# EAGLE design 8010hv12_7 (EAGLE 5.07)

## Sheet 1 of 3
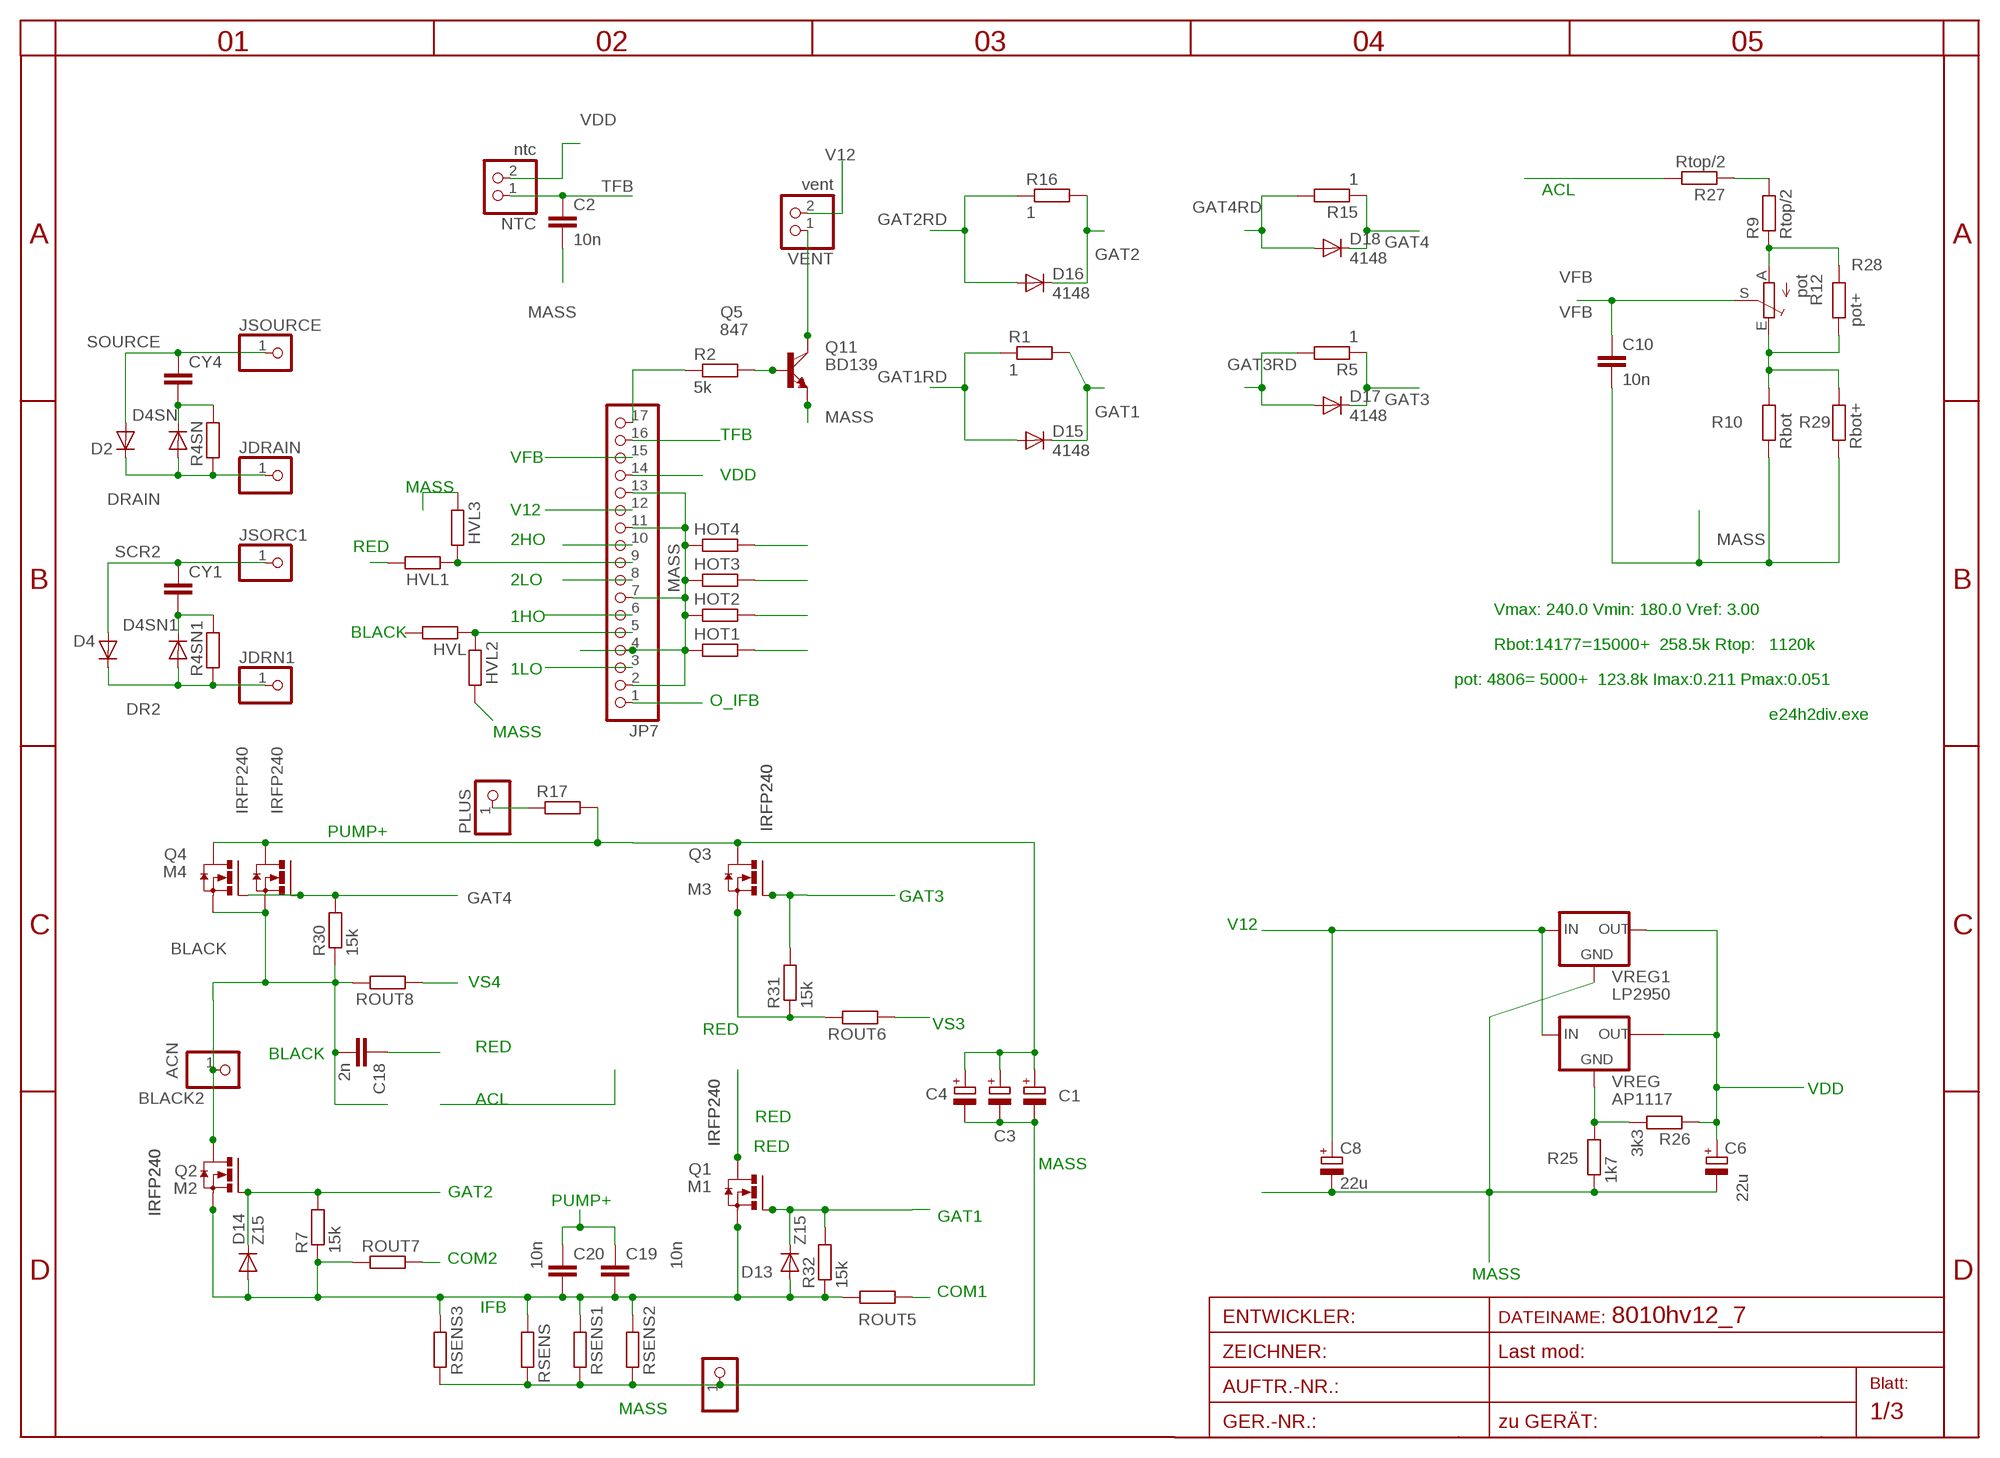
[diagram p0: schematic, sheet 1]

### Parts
BLACK2  ACN  PINHD-1X12MM2  [1X2MM2]
C1  CPOL-EUE5-13  [E5-13]
C2  10n  C-EUC0805  [C0805]
C3  CPOL-EUE5-13  [E5-13]
C4  CPOL-EUE5-13  [E5-13]
C6  22u  CPOL-EUSMCA  [SMC_A]
C8  22u  CPOL-EUSMCA  [SMC_A]
C10  10n  C-EUC0805  [C0805]
C18  2n  C-EU050-024X044  [C050-024X044]
C19  10n  C-EU050-024X044  [C050-024X044]
C20  10n  C-EU050-024X044  [C050-024X044]
CY1  CXXC10B5  [XC10B5]
CY4  CXXC10B5  [XC10B5]
D2  DIODE-TO220V  [TO220ACS]
D4  DIODE-TO220V  [TO220ACS]
D4SN  DIODE-P1-10  [P1-10]
D4SN1  DIODE-P1-10  [P1-10]
D13  Z15  DIODE-MINIMELF  [MINIMELF]
D14  Z15  DIODE-MINIMELF  [MINIMELF]
D15  4148  DIODE-MINIMELF  [MINIMELF]
D16  4148  DIODE-MINIMELF  [MINIMELF]
D17  4148  DIODE-MINIMELF  [MINIMELF]
D18  4148  DIODE-MINIMELF  [MINIMELF]
HOT1  R-EU_R0805  [R0805]
HOT2  R-EU_R0805  [R0805]
HOT3  R-EU_R0805  [R0805]
HOT4  R-EU_R0805  [R0805]
HVL  R-EU_R1005  [R1005]
HVL1  R-EU_R1005  [R1005]
HVL2  R-EU_R0805  [R0805]
HVL3  R-EU_R0805  [R0805]
JDRAIN  PINHD-1X11MM0  [1X1MM0]
JDRN1  PINHD-1X11MM0  [1X1MM0]
JP7  PINHD-1X17  [1X17]
JSORC1  PINHD-1X11MM0  [1X1MM0]
JSOURCE  PINHD-1X11MM0  [1X1MM0]
M1  IRFP240  [TO247BV]
M2  IRFP240  [TO247BV]
M3  IRFP240  [TO247BV]
M4  IRFP240  [TO247BV]
MINUS  PINHD-1X12MM3  [1X2MM3]
NTC  ntc  PINHD-1X2STR  [1X02]
PLUS  PINHD-1X12MM3  [1X2MM3]
Q1  IRFP240  [TO247BV]
Q2  IRFP240  [TO247BV]
Q3  IRFP240  [TO247BV]
Q4  IRFP240  [TO247BV]
Q5  847  BC847SMD  [SOT23]
Q11  BD139  [TO126AV]
R1  1  R-EU_R2512  [R2512]
R2  5k  R-EU_R0805  [R0805]
R4SN  R-EU_0207/10  [0207/10]
R4SN1  R-EU_0207/10  [0207/10]
R5  1  R-EU_R2512  [R2512]
R7  15k  R-EU_R1206  [R1206]
R9  Rtop/2  R-EU_R1206  [R1206]
R10  Rbot  R-EU_R0805  [R0805]
R12  pot  TRIM_EU-B64Y  [B64Y]
R15  1  R-EU_R2512  [R2512]
R16  1  R-EU_R2512  [R2512]
R17  R-EU_0309/10  [0309/10]
R25  1k7  R-EU_R0805  [R0805]
R26  3k3  R-EU_R0805  [R0805]
R27  Rtop/2  R-EU_R1206  [R1206]
R28  pot+  R-EU_R0805  [R0805]
R29  Rbot+  R-EU_R0805  [R0805]
R30  15k  R-EU_R1206  [R1206]
R31  15k  R-EU_R1206  [R1206]
R32  15k  R-EU_R1206  [R1206]
ROUT5  R-EU_R2512  [R2512]
ROUT6  R-EU_R2512  [R2512]
ROUT7  R-EU_R2512  [R2512]
ROUT8  R-EU_R2512  [R2512]
RSENS  R-EU_WIRE  [WIRE]
RSENS1  R-EU_0309/10  [0309/10]
RSENS2  R-EU_0309/12  [0309/12]
RSENS3  R-EU_R2512  [R2512]
VENT  vent  PINHD-1X2STR  [1X02]
VREG  AP1117  [SOT223]
VREG1  LP2950  LP2950TO92-2MIL  [TO92-2MIL]

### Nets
1HO: HOT2.2 JP7.6 ; also sheet 3
1LO: HOT1.2 JP7.3 ; also sheet 3
2HO: HOT4.2 JP7.10 ; also sheet 3
2LO: HOT3.2 JP7.8 ; also sheet 3
ACL: R27.2
BLACK: BLACK2.1 C18.2 HVL.2 M2.D M4.S Q2.D Q4.S R30.1 ROUT8.2
COM1: ROUT5.1 ; also sheet 3
COM2: ROUT7.2 ; also sheet 3
DFG: HVL1.1 HVL3.2 JP7.9
DR2: D4.C D4SN1.A JDRN1.1 R4SN1.1
DRAIN: D2.C D4SN.A JDRAIN.1 R4SN.1
GAT1: D13.C D15.C M1.G Q1.G R1.2 R32.2
GAT1RD: D15.A R1.1 ; also sheet 3
GAT2: D14.C D16.C M2.G Q2.G R7.2 R16.2
GAT2RD: D16.A R16.1 ; also sheet 3
GAT3: D17.C M3.G Q3.G R5.1 R31.2
GAT3RD: D17.A R5.2 ; also sheet 3
GAT4: D18.C M4.G Q4.G R15.1 R30.2
GAT4RD: D18.A R15.2 ; also sheet 3
IFB: C19.2 C20.2 D13.A D14.A M1.S M2.S Q1.S Q2.S R7.1 R32.1 ROUT5.2 ROUT7.1 RSENS1.1 RSENS2.1 RSENS3.1 RSENS.1 ; also sheet 3
JDH: HVL2.1 HVL.1 JP7.5
MASS: C1.- C2.2 C3.- C4.- C6.- C8.- C10.2 HOT1.1 HOT2.1 HOT3.1 HOT4.1 HVL2.2 HVL3.1 JP7.2 JP7.4 JP7.7 JP7.11 JP7.13 MINUS.1 Q5.2(E) Q11.E R10.1 R25.1 R29.1 RSENS1.2 RSENS2.2 RSENS3.2 RSENS.2 VREG1.2(GND) ; also sheet 2,3
N$1: Q5.3(C) Q11.C VENT.1
N$2: Q5.1(B) Q11.B R2.2
N$3: JP7.17 R2.1
N$5: PLUS.1 R17.1
N$17: R25.2 R26.2 VREG.1(GND)
N$23: R9.2 R27.1
N$29: R10.2 R12.E R28.1 R29.2
N$30: R9.1 R12.A R28.2
O_IFB: JP7.1 ; also sheet 3
PUMP+: C1.+ C3.+ C4.+ C19.1 C20.1 M3.D M4.D Q3.D Q4.D R17.2 ; also sheet 2
RED: C18.1 HVL1.2 M1.D M3.S Q1.D Q3.S R31.1 ROUT6.2
SCR2: CY1.1 D4.A JSORC1.1
SNUB1: CY1.2 D4SN1.C R4SN1.2
SNUB2: CY4.2 D4SN.C R4SN.2
SOURCE: CY4.1 D2.A JSOURCE.1
TFB: C2.1 JP7.16 NTC.1
V12: C8.+ JP7.12 VENT.2 VREG1.3(IN) VREG.3(IN) ; also sheet 2,3
VDD: C6.+ JP7.14 NTC.2 R26.1 VREG1.1(OUT) VREG.4(TAB) ; also sheet 3
VFB: C10.1 JP7.15 R12.S
VS3: ROUT6.1 ; also sheet 3
VS4: ROUT8.1 ; also sheet 3
Unconnected: VREG.2(OUT)

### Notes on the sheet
- Vmax: 240.0 Vmin: 180.0 Vref: 3.00
- Rbot:14177=15000+  258.5k Rtop:   1120k
- pot: 4806= 5000+  123.8k Imax:0.211 Pmax:0.051
- e24h2div.exe

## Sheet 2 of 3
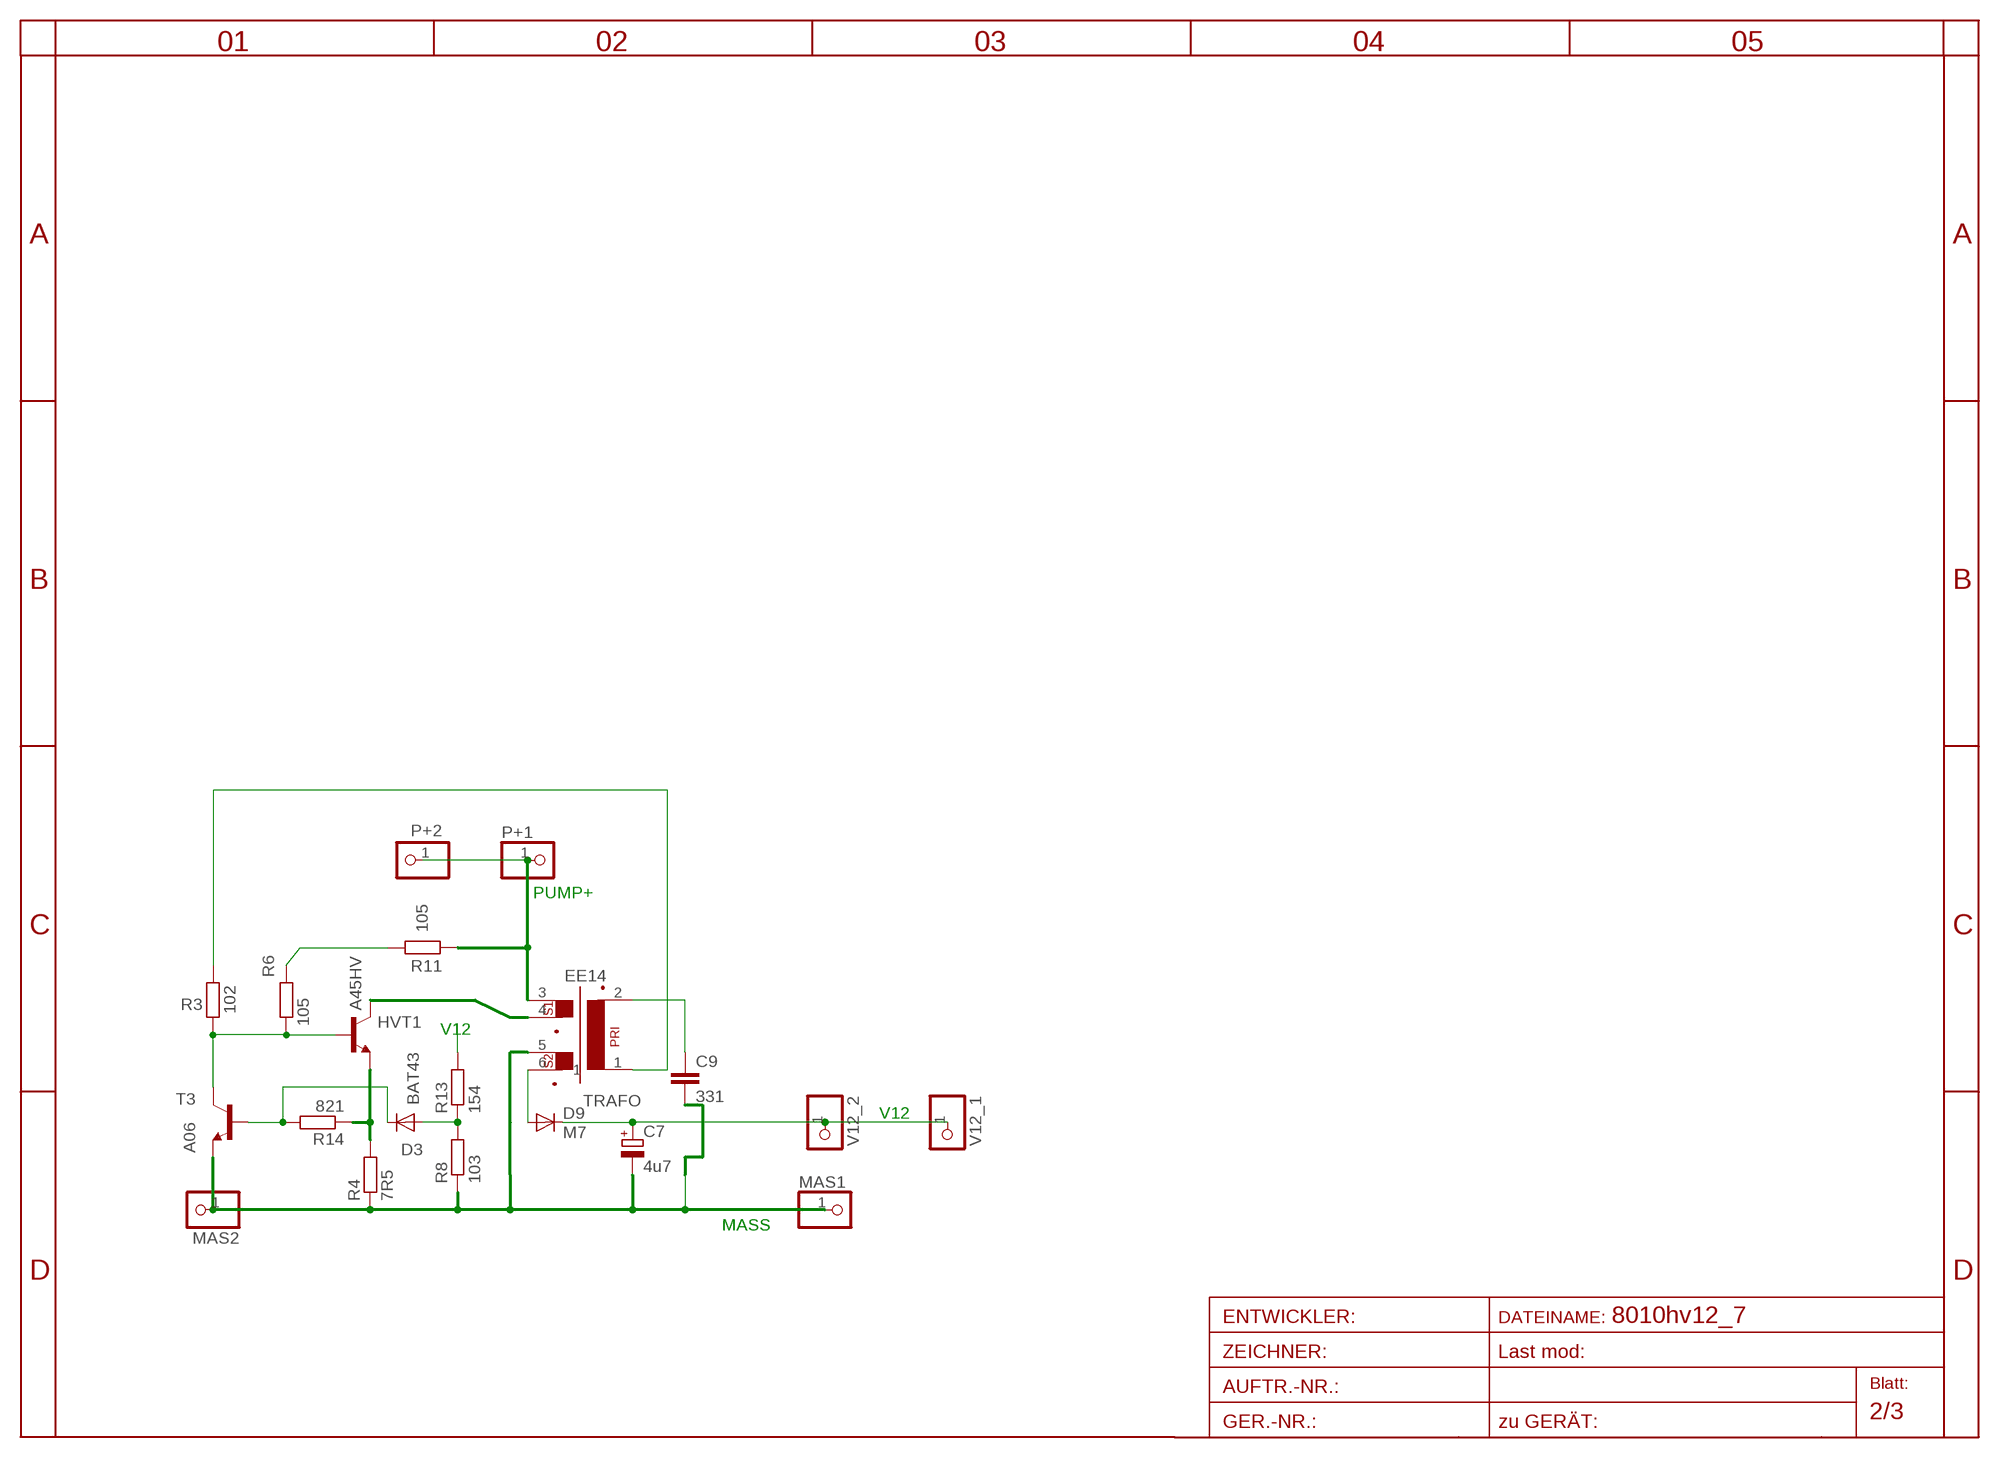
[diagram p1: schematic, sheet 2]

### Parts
C7  4u7  CPOL-EUSMCA  [SMC_A]
C9  331  C-EUC0805  [C0805]
D3  BAT43  DIODE-MINIMELF  [MINIMELF]
D9  M7  DIODE-SMA-DO214  [SMA-DO214AC]
HVT1  A45HV  SMBTA45HV  [SOT23HV]
MAS1  PINHD-1X11X0.4  [1X01]
MAS2  PINHD-1X11X0.4  [1X01]
P+1  PINHD-1X11X0.4  [1X01]
P+2  PINHD-1X11X0.4  [1X01]
R3  102  R-EU_R0805  [R0805]
R4  7R5  R-EU_R0805  [R0805]
R6  105  R-EU_R1206  [R1206]
R8  103  R-EU_R0805  [R0805]
R11  105  R-EU_R1206  [R1206]
R13  154  R-EU_R0805  [R0805]
R14  821  R-EU_R0805  [R0805]
T3  A06  BC848  [SOT23]
TRAFO  EE14  EE14EE14  [EE14]
V12_1  PINHD-1X11X0.4  [1X01]
V12_2  PINHD-1X11X0.4  [1X01]

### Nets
A: D9.A TRAFO.6
B1C2: HVT1.1(B) R3.1 R6.1 T3.C
BT1: D3.C R14.2 T3.B
C1: HVT1.3(C) TRAFO.4
EB: HVT1.2(E) R4.2 R14.1
MASS: C7.- C9.2 MAS1.1 MAS2.1 R4.1 R8.1 T3.E TRAFO.5 ; also sheet 1,3
N$6: R3.2 TRAFO.1
N$7: C9.1 TRAFO.2
N$8: R6.2 R11.2
N$10: D3.A R8.2 R13.1
PUMP+: P+1.1 P+2.1 R11.1 TRAFO.3 ; also sheet 1
V12: C7.+ D9.K(C) R13.2 V12_1.1 V12_2.1 ; also sheet 1,3

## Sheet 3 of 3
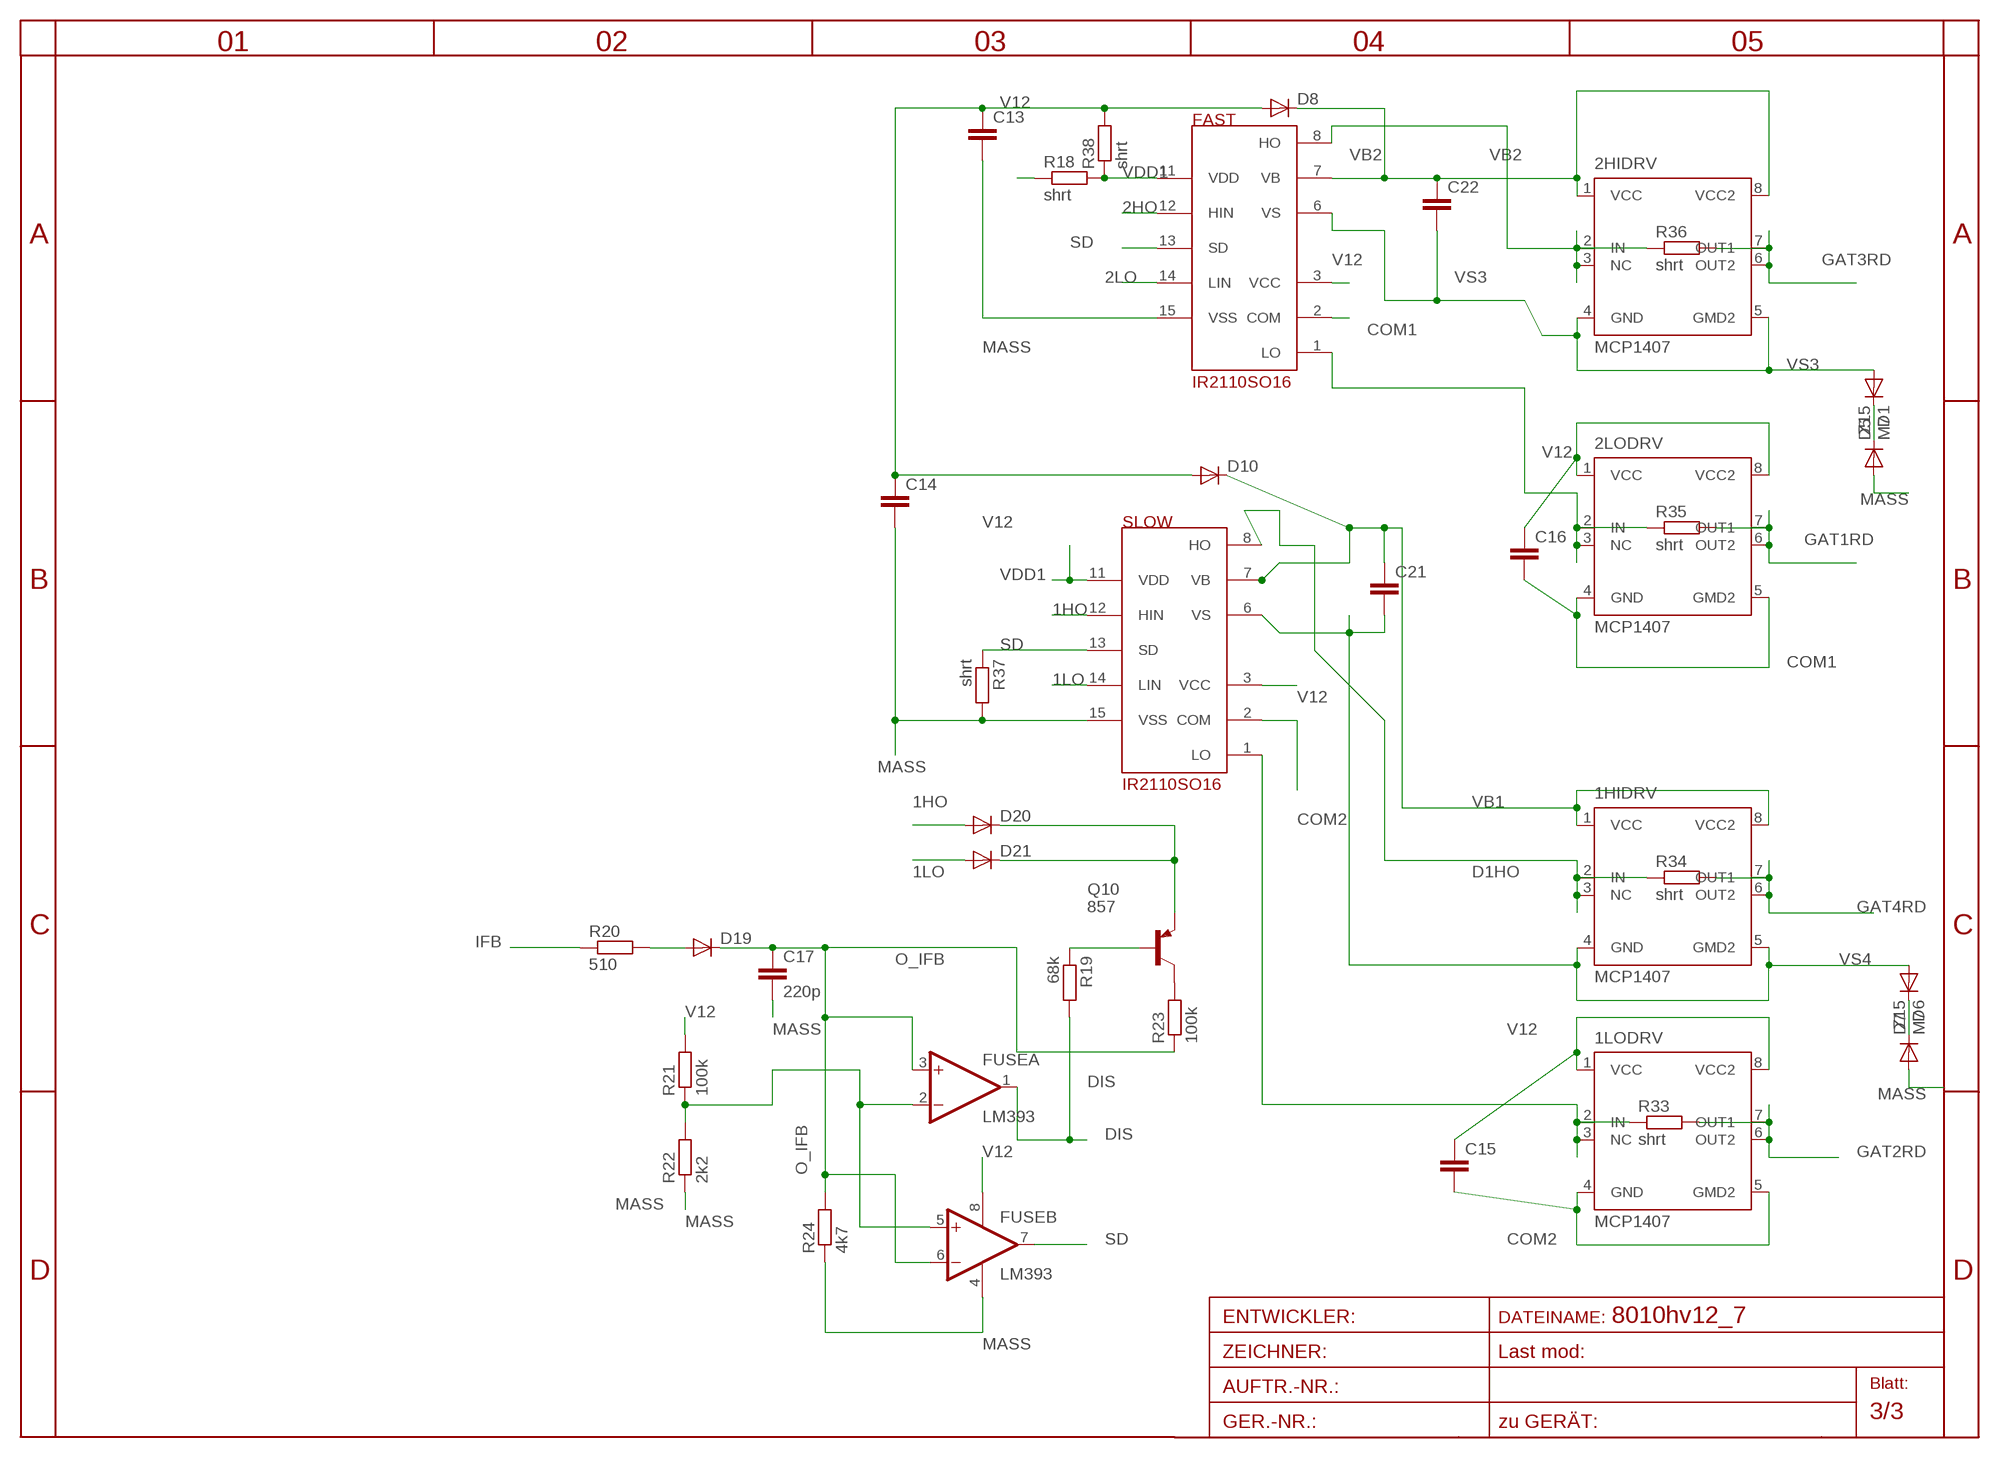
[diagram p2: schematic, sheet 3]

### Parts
1HIDRV  MCP1407  [SO-08M]
1LODRV  MCP1407  [SO-08M]
2HIDRV  MCP1407  [SO-08M]
2LODRV  MCP1407  [SO-08M]
C13  C-EUC1206  [C1206]
C14  C-EUC1206  [C1206]
C15  C-EUC1206  [C1206]
C16  C-EUC1206  [C1206]
C17  220p  C-EUC0805  [C0805]
C21  C-EUC1206  [C1206]
C22  C-EUC1206  [C1206]
D1  Z15  DIODE-MINIMELF  [MINIMELF]
D5  M7  DIODE-SMA-DO214  [SMA-DO214AC]
D6  Z15  DIODE-MINIMELF  [MINIMELF]
D7  M7  DIODE-SMA-DO214  [SMA-DO214AC]
D8  DIODE-SMA-DO214  [SMA-DO214AC]
D10  DIODE-SMA-DO214  [SMA-DO214AC]
D19  DIODE-SOT23  [SOT23]
D20  DIODE-SOT23  [SOT23]
D21  DIODE-SOT23  [SOT23]
FAST  IR2110SO16  [SO16DW]
FUSE  LM393  LM358D  [SO08]
Q10  857  BC857ALT1SMD  [SOT23-BEC]
R18  shrt  R-EU_R0402  [R0402]
R19  68k  R-EU_R0805  [R0805]
R20  510  R-EU_R0805  [R0805]
R21  100k  R-EU_R0805  [R0805]
R22  2k2  R-EU_R0805  [R0805]
R23  100k  R-EU_R0805  [R0805]
R24  4k7  R-EU_R0805  [R0805]
R33  shrt  R-EU_R1206  [R1206]
R34  shrt  R-EU_R1206  [R1206]
R35  shrt  R-EU_R1206  [R1206]
R36  shrt  R-EU_R1206  [R1206]
R37  shrt  R-EU_R0805  [R0805]
R38  shrt  R-EU_R0402  [R0402]
SLOW  IR2110SO16  [SO16DW]

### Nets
1HO: D20.1(A) SLOW.12(HIN) ; also sheet 1
1LO: D21.1(A) SLOW.14(LIN) ; also sheet 1
2HO: FAST.12(HIN) ; also sheet 1
2LO: FAST.14(LIN) ; also sheet 1
COM1: 2LODRV.4(GND) 2LODRV.5(GMD2) C16.2 FAST.2(COM) ; also sheet 1
COM2: 1LODRV.4(GND) 1LODRV.5(GMD2) C15.2 SLOW.2(COM) ; also sheet 1
D1HO: 1HIDRV.2(IN) 1HIDRV.3(NC) R34.1 SLOW.8(HO)
D1LO: 1LODRV.2(IN) 1LODRV.3(NC) R33.1 SLOW.1(LO)
DIS: FUSE.1(A:OUT) R19.2
GAT1RD: 2LODRV.6(OUT2) 2LODRV.7(OUT1) R35.2 ; also sheet 1
GAT2RD: 1LODRV.6(OUT2) 1LODRV.7(OUT1) R33.2 ; also sheet 1
GAT3RD: 2HIDRV.6(OUT2) 2HIDRV.7(OUT1) R36.2 ; also sheet 1
GAT4RD: 1HIDRV.6(OUT2) 1HIDRV.7(OUT1) R34.2 ; also sheet 1
IFB: R20.1 ; also sheet 1
MASS: C13.2 C14.2 C17.2 D5.A D7.A FAST.15(VSS) FUSE.4(P:V-) R22.1 R24.1 R37.2 SLOW.15(VSS) ; also sheet 1,2
N$9: FUSE.2(A:-IN) FUSE.5(B:+IN) R21.1 R22.2
N$12: 2HIDRV.2(IN) 2HIDRV.3(NC) FAST.8(HO) R36.1
N$14: D19.1(A) R20.2
N$16: 2LODRV.2(IN) 2LODRV.3(NC) FAST.1(LO) R35.1
N$18: D20.3(C) D21.3(C) Q10.E
N$20: D1.C D5.K(C)
N$24: D6.C D7.K(C)
N$25: Q10.B R19.1
N$26: Q10.C R23.2
O_IFB: C17.1 D19.3(C) FUSE.3(A:+IN) FUSE.6(B:-IN) R23.1 R24.2 ; also sheet 1
SD: FAST.13(SD) FUSE.7(B:OUT) R37.1 SLOW.13(SD)
V12: 1LODRV.1(VCC) 1LODRV.8(VCC2) 2LODRV.1(VCC) 2LODRV.8(VCC2) C13.1 C14.1 C15.1 C16.1 D8.A D10.A FAST.3(VCC) FUSE.8(P:V+) R21.2 R38.2 SLOW.3(VCC) ; also sheet 1,2
VB1: 1HIDRV.1(VCC) 1HIDRV.8(VCC2) C21.1 D10.K(C) SLOW.7(VB)
VB2: 2HIDRV.1(VCC) 2HIDRV.8(VCC2) C22.1 D8.K(C) FAST.7(VB)
VDD: R18.1 ; also sheet 1
VDD1: FAST.11(VDD) R18.2 R38.1 SLOW.11(VDD)
VS3: 2HIDRV.4(GND) 2HIDRV.5(GMD2) C22.2 D1.A FAST.6(VS) ; also sheet 1
VS4: 1HIDRV.4(GND) 1HIDRV.5(GMD2) C21.2 D6.A SLOW.6(VS) ; also sheet 1

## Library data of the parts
1HIDRV 1LODRV 2HIDRV 2LODRV = microchip:MCP1407
BLACK2 JDRAIN JDRN1 JSORC1 JSOURCE MAS1 MAS2 MINUS P+1 P+2 PLUS V12_1 V12_2 = pinhead:PINHD-1X1: PIN HEADER
C1 C3 C4 C6-C8 = rcl:CPOL-EU: POLARIZED CAPACITOR, European symbol
C2 C9 C10 C13-C22 = rcl:C-EU: CAPACITOR, European symbol
CY1 CY4 = rcl:CX: X CAPACITOR
D1-D4 D4SN D4SN1 D5-D10 D13-D21 = diode:DIODE-: DIODE
FAST SLOW = ir2112:IR2110
FUSE = linear:LM358: OP AMP also LM158; LM258; LM2904 Source: http://cache.national.com/ds/LM/LM158.pdf
HOT1-HOT4 HVL HVL1-HVL3 R1-R4 R4SN R4SN1 R5-R8 R11 R13-R17 R19-R24 R30-R32 ROUT5-ROUT8 RSENS RSENS1-RSENS3 = rcl:R-EU_: RESISTOR, European symbol
HVT1 = transistor-npn:SMBTA45
JP7 = pinhead:PINHD-1X17: PIN HEADER
M1-M4 Q1-Q4 = transistor-power:IRFP240: HEXFET Power MosFet Source: http://www.irf.com/
NTC VENT = pinhead:PINHD-1X2: PIN HEADER
Q5 = transistor-npn:BC847*: NPN Transistor
Q10 = transistor-pnp:BC857*: PNP Transistror
Q11 = transistor-power:BD139: NPN TRANSISTOR
R9 R10 R25-R29 = rcl-2:R-EU_: RESISTOR, European symbol
R12 = pot:TRIM_EU-: POTENTIOMETER
R18 R33-R38 = rcl(2):R-EU_: RESISTOR, European symbol
T3 = transistor:BC848: NPN TRANSISTOR
TRAFO = trafo:EE14
VREG = v-reg:AP1117
VREG1 = v-reg:LP2950?*: Source: http://cache.national.com/ds/LP/LP2950.pdf

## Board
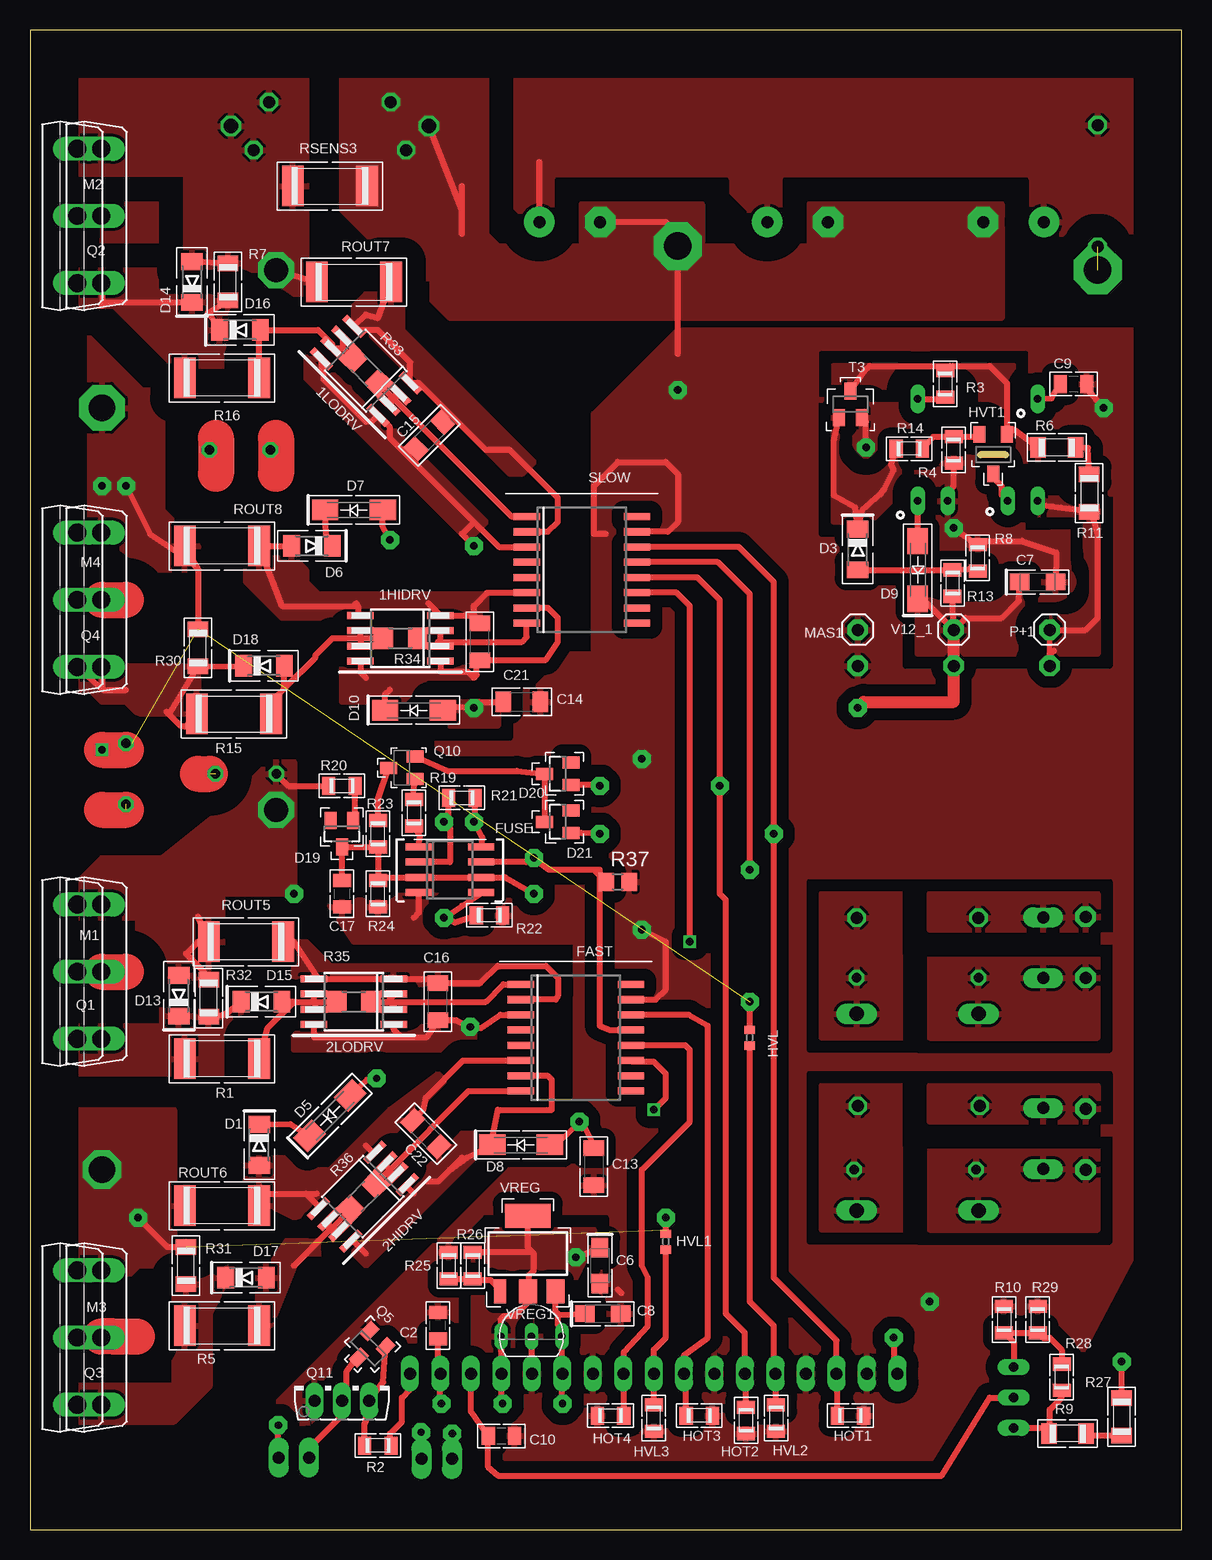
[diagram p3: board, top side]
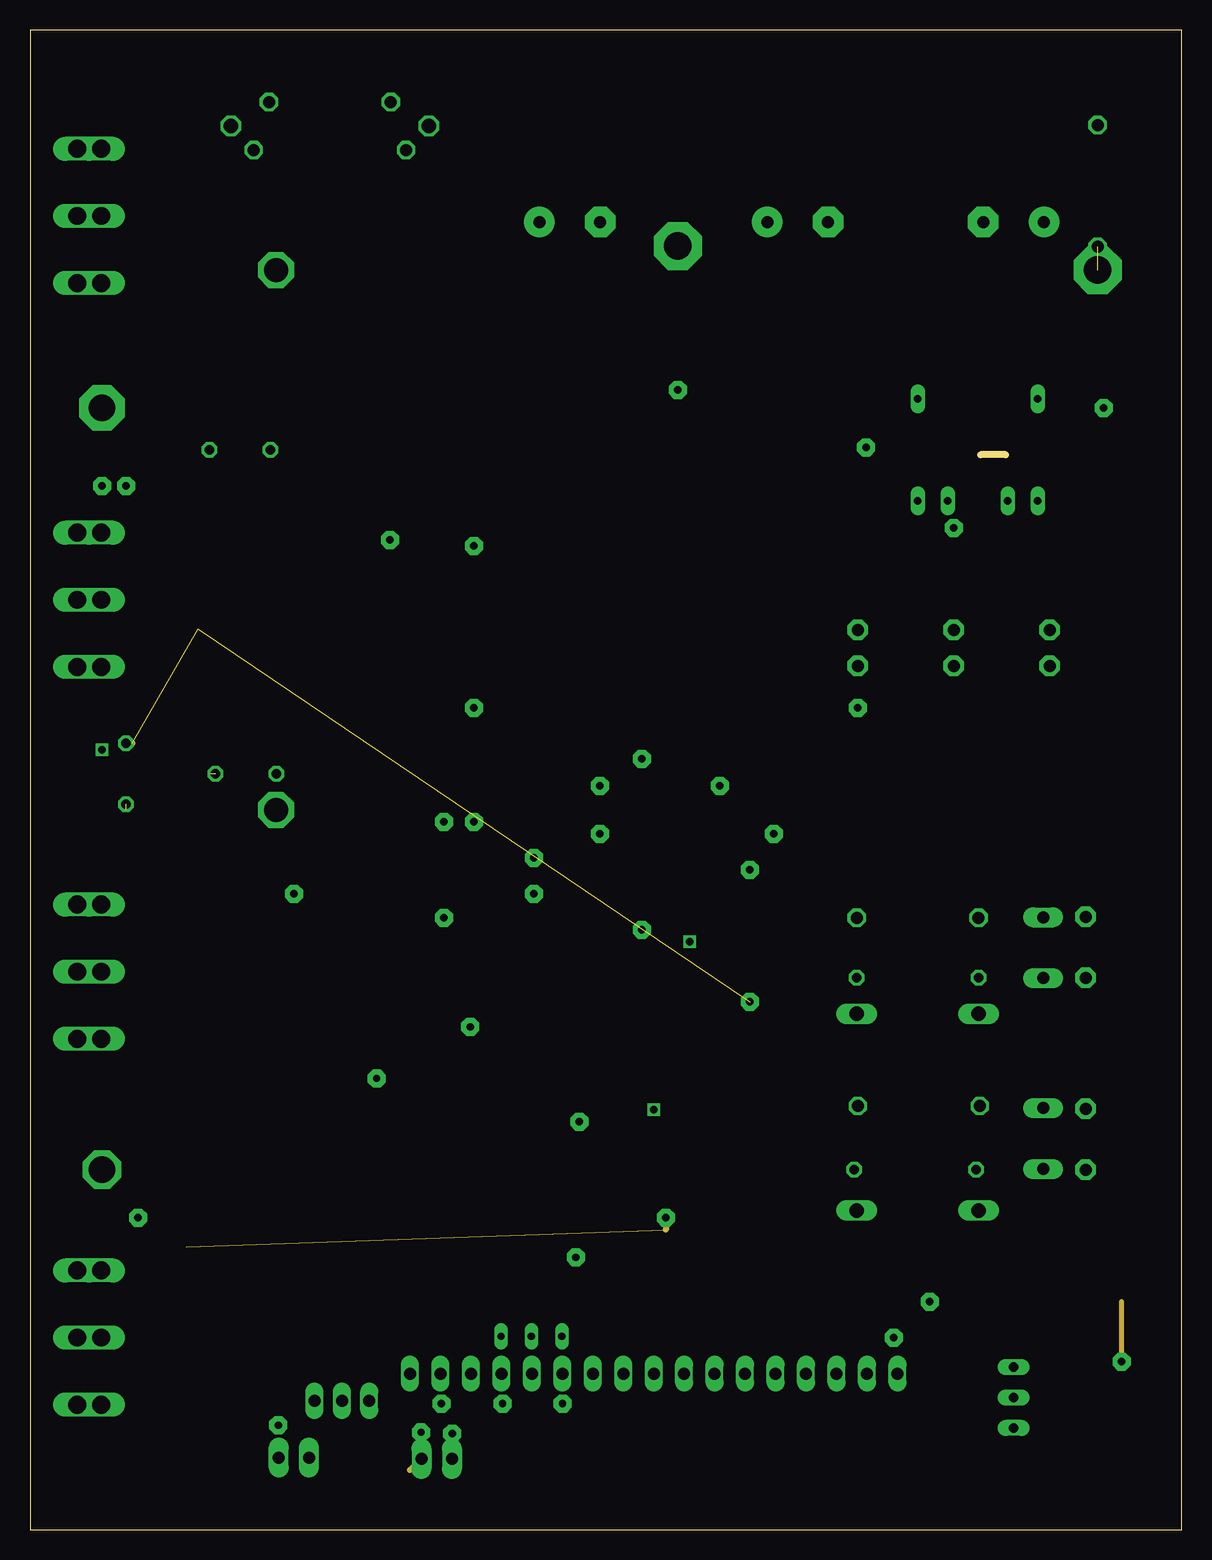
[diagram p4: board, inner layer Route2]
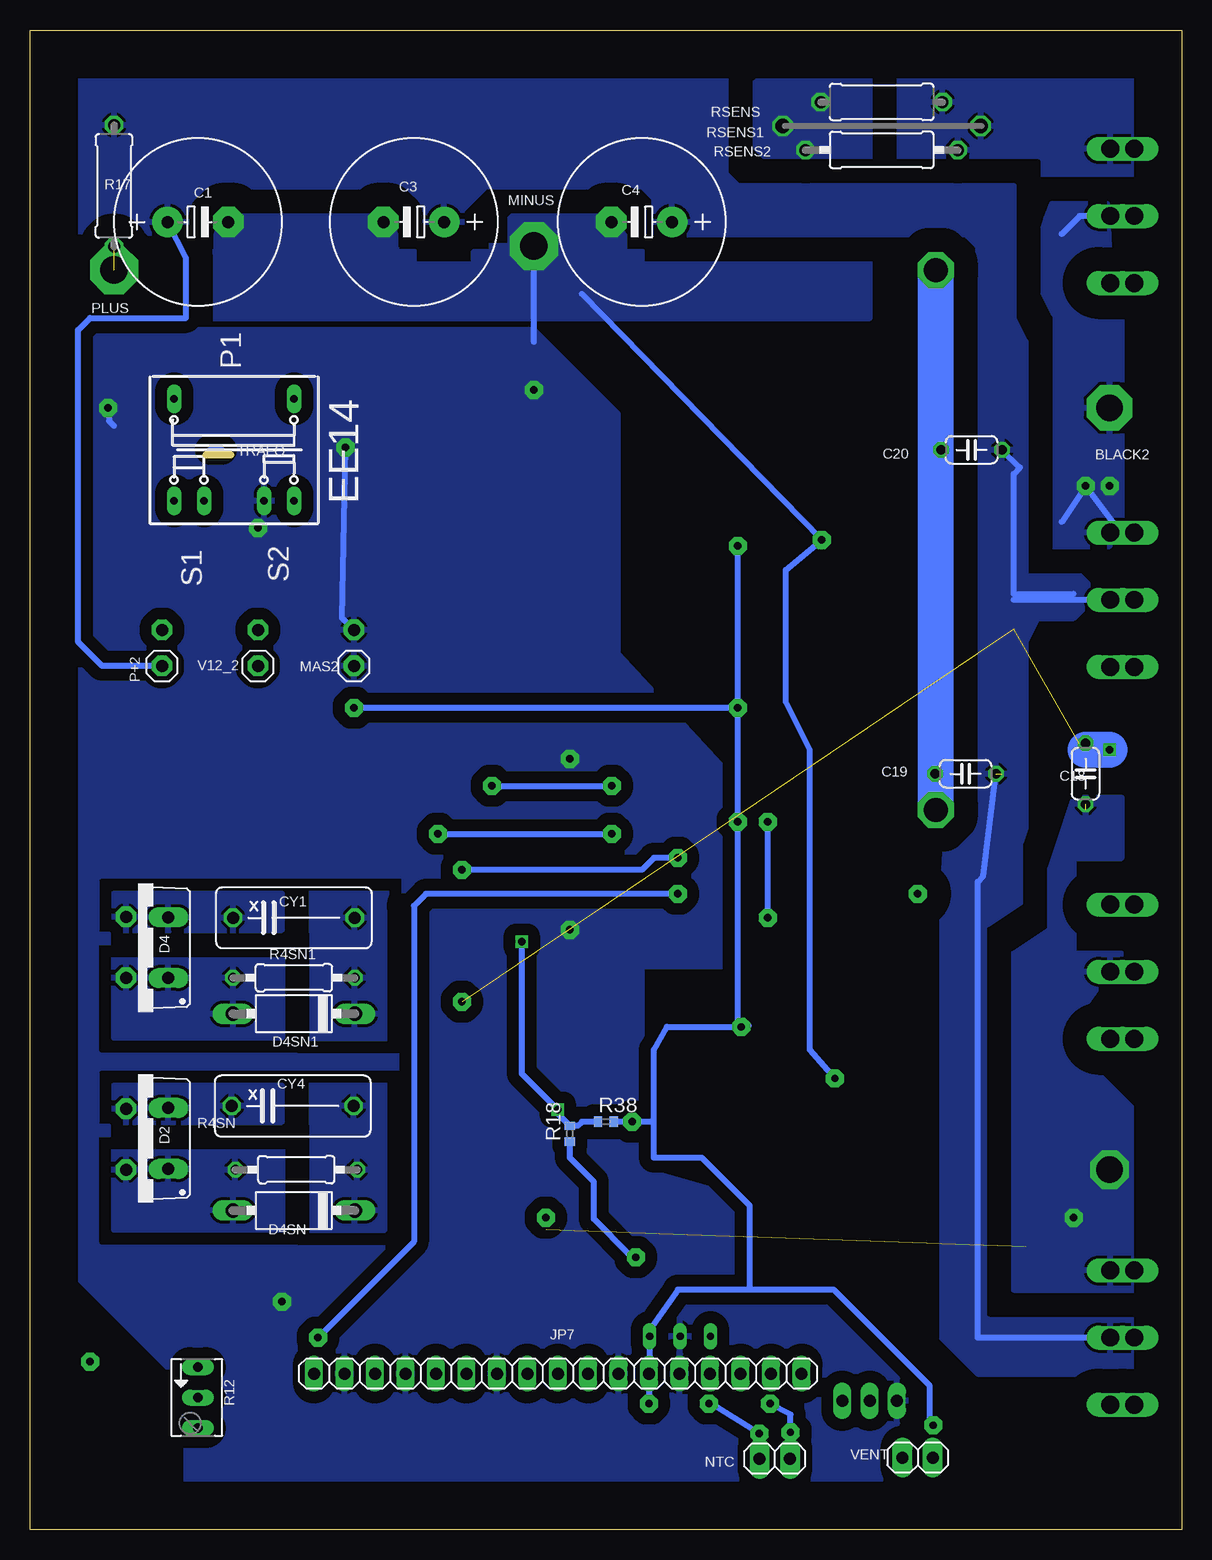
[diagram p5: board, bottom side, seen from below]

Size 96 x 125 mm. Coordinates in mm from the lower left corner, seen from the top.
Outline: 0,0 96,0 96,125 0,125 0,0
Copper layers (1*16): Top 0.035mm / dielectric 1.5mm / Bottom 0.035mm
Design rules "default *": minimum track width 10mil, minimum drill 20mil, track to track 8mil, track to pad 8mil, pad to pad 8mil, via to via 8mil, smd to smd 8mil, copper to edge 4mm, drill to drill 8mil, minimum pad ring 10mil, minimum via ring 8mil, stop-mask expansion 4mil, vias tented up to drill 0mil, thermal gap 10mil

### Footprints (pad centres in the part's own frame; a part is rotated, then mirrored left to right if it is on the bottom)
SO-08M = smd 0.6 x 2.2: 1 -1.905,-3.33; 2 -0.635,-3.33; 3 0.635,-3.33; 4 1.905,-3.33; 5 1.905,3.33; 6 0.635,3.33; 7 -0.635,3.33; 8 -1.905,3.33
1X2MM2 = drill 2.2 pad 3.81 octagon: 1 0,0
E5-13 = drill 1 pad 2.54 round: + -2.54,0 | drill 1 pad 2.54 octagon: - 2.54,0
C0805 = smd 1.1 x 1.5: 1 -1.1,0; 2 1.1,0
SMC_A = smd 1.6 x 1.4: + -1.5,0; - 1.5,0
C1206 = smd 1.3 x 1.7: 1 -1.55,0; 2 1.55,0
C050-024X044 = drill 0.8 octagon: 1 -2.54,0; 2 2.54,0
XC10B5 = drill 1 octagon: 1 -5.08,0; 2 5.08,0
MINIMELF = smd 1.4 x 1.8: A 1.7,0; C -1.7,0
TO220ACS = drill 1 pad 1.676 long: A 2.54,-2.54; C -2.54,-2.54
P1-10 = drill 1.2 long: A 5.08,0; C -5.08,0
SMA-DO214AC = smd 2.2 x 1.7: A 2.4,0; K -2.4,0
SOT23 = smd 1 x 1.4: 1 -0.95,-1.1; 2 0.95,-1.1; 3 0,1.1
SO16DW = smd 0.6 x 2.2: 1 -4.445,-4.6; 2 -3.175,-4.6; 3 -1.905,-4.6; 4 -0.635,-4.6; 5 0.635,-4.6; 6 1.905,-4.6; 7 3.175,-4.6; 8 4.445,-4.6; 9 4.445,4.6; 10 3.175,4.6; 11 1.905,4.6; 12 0.635,4.6; 13 -0.635,4.6; 14 -1.905,4.6; 15 -3.175,4.6; 16 -4.445,4.6
SO08 = smd 0.6 x 2.2: 1 -1.905,-2.6; 2 -0.635,-2.6; 3 0.635,-2.6; 4 1.905,-2.6; 5 1.905,2.6; 6 0.635,2.6; 7 -0.635,2.6; 8 -1.905,2.6
R0805 = smd 1.1 x 1.5: 1 -1.1,0; 2 1.1,0
R1005 = smd 0.7 x 0.9: 1 -0.65,0; 2 0.65,0
SOT23HV = smd 1 x 1.4: 1 -1.15,-1.7; 2 1.15,-1.7; 3 0,1.6
1X1MM0 = drill 1 pad 1.676 octagon: 1 0,0
1X17 = drill 1 long: 1 -20.32,0; 2 -17.78,0; 3 -15.24,0; 4 -12.7,0; 5 -10.16,0; 6 -7.62,0; 7 -5.08,0; 8 -2.54,0; 9 0,0; 10 2.54,0; 11 5.08,0; 12 7.62,0; 13 10.16,0; 14 12.7,0; 15 15.24,0; 16 17.78,0; 17 20.32,0
TO247BV = drill 1.499 long: D 0,-2.921; G -5.588,-2.921; S 5.588,-2.921
1X01 = drill 1 pad 1.676 octagon: 1 0,0
1X2MM3 = drill 2.3 pad 4 octagon: 1 0,0
1X02 = drill 1 pad 1.676 long: 1 -1.27,0; 2 1.27,0
SOT23-BEC = smd 1 x 1.4: B -0.95,-1.1; C 0,1.1; E 0.95,-1.1
TO126AV = drill 1 pad 1.27 long: B 2.286,-1.27; C 0,-1.27; E -2.286,-1.27
R2512 = smd 1.8 x 3.4: 1 -3.1,0; 2 3.1,0
0207/10 = drill 0.8 octagon: 1 -5.08,0; 2 5.08,0
R1206 = smd 1.3 x 1.7: 1 -1.55,0; 2 1.55,0
B64Y = drill 0.813 long: A 2.54,0; E -2.54,0; S 0,0
0309/10 = drill 1 octagon: 1 -5.08,0; 2 5.08,0
R0402 = smd 0.7 x 0.9: 1 -0.65,0; 2 0.65,0
R1206' = smd 1.6 x 1.803: 1 -1.422,0; 2 1.422,0
R0805' = smd 1.3 x 1.5: 1 -0.95,0; 2 0.95,0
WIRE = drill 1.2 octagon: 1 -8.25,0; 2 8.25,0
0309/12 = drill 1 octagon: 1 -6.35,0; 2 6.35,0
SOT23' = smd 1 x 1.4: B -0.95,-1.1; C 0,1.1; E 0.95,-1.1
EE14 = drill 0.6 pad 1.2 long: 1 4.25,-5; 2 4.25,5; 3 -4.25,5; 4 -4.25,2.5; 5 -4.25,-2.5; 6 -4.25,-5
SOT223 = smd 1 x 2: 1 -2.3,-3.15 | smd 1.5 x 2: 2 0,-3.15; 3 2.3,-3.15 | smd 3.8 x 2: 4 0,3.15
TO92-2MIL = drill 0.6 pad 0.813 long: 1 -2.54,0; 2 0,0; 3 2.54,0

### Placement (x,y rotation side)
1HIDRV  30.88,74.29 90 top
1LODRV  28,96.59 45 top
2HIDRV  27.75,27.75 135 top
2LODRV  27,44 90 top
BLACK2  6,93.5 180 bottom
C1  82,109 0 bottom
C2  34,17 90 top
C3  64,109 180 bottom
C4  45,109 180 bottom
C6  47.5,22 270 top
C7  84,79 0 top
C8  47.75,18 0 top
C9  87,95.5 0 top
C10  39.3,7.8 0 top
C13  47,30.25 270 top
C14  41,69 0 top
C15  33.3,91.2 45 top
C16  34,44 90 top
C17  26,53 270 top
C18  8,63 90 bottom
C19  18,63 180 bottom
C20  17.5,90 180 bottom
C21  37.5,74 90 top
C22  33,33 135 top
CY1  74,51 0 bottom
CY4  74.1,35.3 0 bottom
D1  19.12,32.06 270 top
D2  87,32.6 90 bottom
D3  69,81.7 270 top
D4  87,48.5 90 bottom
D4SN  74,26.6 180 bottom
D4SN1  74,43 180 bottom
D5  25,34.5 45 top
D6  23.5,82 180 top
D7  27,85 0 top
D8  40.93,32.07 0 top
D9  74,80 90 top
D10  32,68.3 0 top
D13  12.4,44.5 90 top
D14  13.5,104 90 top
D15  19.3,44 0 top
D16  17.5,100 0 top
D17  18,21 0 top
D18  19.5,72 0 top
D19  26,58 180 top
D20  44,63 90 top
D21  44,59 90 top
FAST  45.5,41 270 top
FUSE  35,55 270 top
HOT1  68.4,9.5 180 top
HOT2  59.7,9.1 90 top
HOT3  55.8,9.5 180 top
HOT4  48.4,9.5 0 top
HVL  60,41 90 top
HVL1  53,24 90 top
HVL2  62.2,9.3 270 top
HVL3  52,9.3 90 top
HVT1  80.3,89.6 180 top
JDRAIN  88,30 270 top
JDRN1  88,46 0 top
JP7  52,13 0 bottom
JSORC1  88,51.08 0 top
JSOURCE  88,35.08 270 top
M1  3,46.5 90 top
M2  3,109.5 90 top
M3  3,16 90 top
M4  3,77.5 90 top
MAS1  69,75 270 top
MAS2  69,72 90 bottom
MINUS  54,107 270 bottom
NTC  33.9,5.9 180 bottom
P+1  85,75 270 top
P+2  85,72 90 bottom
PLUS  89,105 270 bottom
Q1  1,46.5 90 top
Q2  1,109.5 90 top
Q3  1,16 90 top
Q4  1,77.5 90 top
Q5  28.2,15.1 135 top
Q10  31,63.5 90 top
Q11  26,12 0 top
R1  16,39.25 180 top
R2  29,7 180 top
R3  76.3,95.5 270 top
R4  77,90 90 top
R4SN  73.8,30 0 bottom
R4SN1  74,46 0 bottom
R5  16,17 0 top
R6  85.6,90.2 0 top
R7  16.5,104 270 top
R8  79,81 270 top
R9  86.5,8 0 top
R10  81.2,17.5 270 top
R11  88.3,86.4 90 top
R12  82,11 270 bottom
R13  76.9,78.9 270 top
R14  73.3,90.1 180 top
R15  17,68 0 top
R16  16,96 180 top
R17  89,112 90 bottom
R18  51,33 90 bottom
R19  32,59.75 270 top
R20  26,62 0 top
R21  36,61 0 top
R22  38.3,51.2 180 top
R23  29,58 90 top
R24  29,53 90 top
R25  34.9,22 270 top
R26  36.9,22 270 top
R27  91,9.4 90 top
R28  86,12.7 270 top
R29  84,17.5 270 top
R30  14,73.5 270 top
R31  13,22 270 top
R32  14.9,44.3 270 top
R33  shrt  [R1206']  28,96.59 135 top
R34  shrt  [R1206']  30.88,74.29 180 top
R35  shrt  [R1206']  27,44 180 top
R36  shrt  [R1206']  27.75,27.75 225 top
R37  shrt  [R0805']  49,54 0 top
R38  48,34 0 bottom
ROUT5  18,49 180 top
ROUT6  16,27 180 top
ROUT7  27,104 0 top
ROUT8  16,82 180 top
RSENS  25,117 180 bottom
RSENS1  25,119 180 bottom
RSENS2  25,115 180 bottom
RSENS3  25,112 0 top
SLOW  46,80 270 top
T3  A06  [SOT23']  68.4,93.8 0 top
TRAFO  79,90 90 bottom
V12_1  77,75 270 top
V12_2  77,72 90 bottom
VENT  22,6 0 bottom
VREG  41.5,23 0 top
VREG1  41.8,16.1 0 top

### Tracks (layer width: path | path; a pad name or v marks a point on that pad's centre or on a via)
1HO  (via drill 0.6 pad 1.5)
  Top 0.5: D20.1 46.95,62.05 v47.5,62 | HOT2.2 59.7,12.92 JP7.6 59.6,14.4 59.6,16.4 58,18 58,52.5 57.5,53 v57.5,62 57.5,73 57.5,77.5 56,79 55.63,79.36 SLOW.12
  Bottom 0.5: v57.5,62 v47.5,62
1LO  (via drill 0.6 pad 1.5)
  Top 0.5: D21.1 46,58.05 v47.5,58 | HOT1.2 67.3,12.94 JP7.3 67.24,15.76 62,21 v62,58 62,79 59.09,81.91 SLOW.14
  Bottom 0.5: v62,58 v47.5,58
2HO
  Top 0.5: HOT4.2 49.5,12.96 JP7.10 49.5,14.8 51.5,17 51.5,21 51,22 51,30 55,34 55,40 54.63,40.37 FAST.12
2LO
  Top 0.5: HOT3.2 54.7,12.84 JP7.8 54.54,14.54 56.5,16 56.5,42 54.91,42.91 FAST.14
A
  Top 0.5: D9.A TRAFO.6
ACL  (via drill 0.6 pad 1.5)
  Top 0.5: R27.2 v91,14
  Route2 0.406: v91,14 91,19
B1C2
  Top 0.5: R6.1 82.05,91.7 HVT1.1 81.45,95.55 80,97 76.9,97 | 76.7,97 R3.1 76.9,97 | T3.C 69.6,96.6 70,97 76.7,97 | 76.7,97 76.9,97
  pour Top (isolate 2): 82,92 82,97 67,97 67,94 80,94 80,92 83,89 85,89 85,91
BLACK  (via drill 0.6 pad 1.5)  (2 unrouted)
  Top 0.5: Q4.S M4.S | v8,87 10,83 13,81 14,80.1 | 14,80.1 ROUT8.2 | HVL.2 v60,44 | 14,80.1 R30.1
  Route2 0.5: C18.2 8.54,65.54
  Bottom 0.5: M2.D 8.5,109.5 10,108 | 10,84 v8,87 5,83
  other vias: 6,87
  pour Bottom (isolate 2, rank 3): 6.2,110.5 10.8,110.5 arc-41 11.4,100.5 11,100 11,82 6,82 6,83 5,84 5,105 6,106
  pour Top (isolate 2, rank 3): 6.2,110.5 10.8,110.5 arc-41 11.4,100.5 11,100 11,85 14,82 14,80 10,80 6,83 5,84 5,105 6,106
BT1
  Top 0.5: T3.B 67,90.75 67,86.2 68.8,85.2 D3.C 69.4,85 70.9,86.3 71.2,86.7 72,88.3 71.8,88.8 R14.2
  pour Top (isolate 1.5, rank 2): 74,90 74,88 70,84 67,84 67,93 69,93 69,92 71,90
C1
  Top 0.5: HVT1.3 80.3,87.7 81,87 81,86.25 TRAFO.4
COM1
  Top 0.5: ROUT5.1 22,49 24,46 23.77,46 2LODRV.5 29.91,45.91 30,46 30.23,46 2LODRV.4 34.65,45.91 C16.2 37.55,45.55 39,47 43,47 44,46 44,44.5 43.83,44.17 FAST.2
  pour Top (isolate 1): 22,49 23,49 25,47 39,47 39,45 37,45 23,45 22,46 22,48
COM2
  Top 0.5: 35,93 38,90 40,90 44,86 44,84 43.17,83.17 SLOW.2 | 35,93 32.42,95.58 1LODRV.4 31.7,97.3 29,100 27.28,100 1LODRV.5 28,101.28 29,101 ROUT7.2 | C15.2 34.4,92.4 35,93
  pour Top (isolate 1): 31,103 31,100 42,89 41,88 40,88 27,101 27,102 28,103
D1HO
  Top 0.5: R34.1 33.06,73.66 1HIDRV.2 | 1HIDRV.2 1HIDRV.3 | SLOW.8 41.4,74.4 41,74 34,74 34,73.87 1HIDRV.2
D1LO
  Top 0.5: 30.12,94.46 29.84,94.75 R33.1 40.14,84.44 SLOW.1 | 1LODRV.3 30.59,94.46 30.12,94.46 | 1LODRV.2 30.12,94 30.12,94.46
DFG
  Top 0.5: HVL1.1 53,16 52,15 JP7.9 HVL3.2
DIS
  Top 0.5: R19.2 32.5,57.8 FUSE.1
DR2
  pour Top (isolate 2, rank 2): 89,48 75,48 75,41 89,41
  pour Bottom (isolate 2, rank 2): 89,48 75,48 75,41 89,41
DRAIN
  pour Top (isolate 2, rank 2): 89,32 75,32 75,25 89,25
  pour Bottom (isolate 2, rank 2): 89,32 75,32 75,25 89,25
EB
  Top 0.5: R14.1 75.3,91.1 R4.2 78.95,91.1 HVT1.2
GAT1
  Top 0.5: R32.2 16.25,42.95 D15.C
  pour Top (isolate 2): 3,42 11,42 11,44 18,44 16,38 3,38
GAT1RD
  Top 0.5: 22,44 23.77,44 | 22,44 19.81,41.81 R1.1 | 2LODRV.6 23.67,44.09 23.77,44 | 23.77,44 23.77,43.46 2LODRV.7 | 22,44 D15.A | 23.77,44 R35.2
GAT2
  Top 0.5: R7.2 14.85,101.45 D16.C | D14.C 6.3,102.3 6,102 6,104 6.07,104 M2.G
  pour Top (isolate 2, rank 2): 2,105 11,105 18,103 18,97 12,97 7,102 2,102
GAT2RD
  Top 0.5: 26.09,98.49 R33.2 | 26.09,98.49 1LODRV.7 25.2,98.8 24,100 D16.A 19.1,100 R16.1 | 26.09,98.49 1LODRV.6
GAT3
  pour Top (isolate 2, rank 3): 3,12 3,9 12,9 15,12 15,18 17,22 12,20 12,12
GAT3RD
  Top 0.5: 22,22 24.95,24.95 | 24.95,24.95 2HIDRV.6 | 24.95,24.95 25,25 | 25,25 R36.2 | 2HIDRV.7 25.05,24.95 25,25
  pour Top (isolate 1.5, rank 2): 22,25 29,28 26,23 23,23 22,22 20,17 19,17 19,22 20,22
GAT4
  Top 0.5: Q4.G 6.07,70 | 6.07,70 8,70 | 11.62,67.95 R30.2 14.75,71.95 D18.C | 11.62,67.95 11.39,68.18 | R15.1 12.9,66.9 13,67 12.57,67 11.62,67.95 | 6.07,70 6.07,71.76 M4.G
  pour Top (isolate 1.5): 2.9,72.5 6.9,72.5 8,72 14,72 14,68 9,68 8,69 6,69 5,70 3,70
GAT4RD
  Top 0.5: 27.55,74.29 1HIDRV.7 | 27.55,74.29 1HIDRV.6 | 27.55,74.29 25.22,74.29 23.81,72.88 23.81,72.71 21.2,70.1 | R15.2 20.1,69 | 20.1,69 20.1,69.1 | 27.55,74.29 R34.2 | 21.2,70.1 D18.A | 20.1,69 21.2,70.1
IFB  (via drill 0.6 pad 1.5, 2 pad 1.5)
  Top 0.5: D14.A 14.35,105.7 R7.1 | 14,51.1 ROUT5.2 14,49 13,48 14.5,46.5 R32.1 | v20.5,105 ROUT7.1 | 20.5,91 20.5,90.46 C20.2 | R20.1 21.54,62 C19.2
  Top 3: 20.5,91 20.5,88
  Bottom 0.5: v20.5,105 20.5,90.46 C20.2
  Bottom 3: v20.5,60 v20.5,105
  other vias: 22,53
  pour Top (isolate 2, rank 2): 3,51 3,54 4,54 6,56 11,56 16,60 20,64 22,64 22,53 16,53 16,46 9,46 9,51
  pour Top (isolate 2): 3,121 23,121 23,103 22,103 19,105 13,105 13,113 4,113 3,114
  pour Bottom (isolate 2, rank 4): 3,121 24,121 24,113 4,113 3,114
JDH
  Top 0.5: HVL.1 60,19 62,17 62,13.16 JP7.5 62.2,12.96 HVL2.1
MASS  (via drill 0.6 pad 1.5)
  Top 0.5: C7.- 85.55,81.45 82.7,82.4 79.8,82.4 R8.1 78.9,82.1 v77,83.5 | C9.2 88.1,95.1 v89.5,93.5 | TRAFO.5 76.5,86.5 77,87 R4.1 | v69.7,90.2 69.7,92.35 T3.E | 36,110 36,112 | 47,109 C4.- 53,109 54,108 54,98 | 36,108 36,110 | 36,110 RSENS.2 | 49,20 49.3,19.7 | FUSE.4 32.4,51.4 32,51 | FAST.15 52.17,44.17 53,45 53,49 v51,50 | D7.A 29.4,83.6 v30,82.5 | SLOW.15 53.17,83.17 54,84 54,88 53,89 49,89 47,87 47,83 48,83 | D5.A 28.1,37.5 v28.9,37.6 | JP7.13 41.84,16.06 VREG1.2
  Bottom 0.5: v69.7,90.2 70,76 MAS1.1 | v89.5,93.5 89.4,92.4 89,92 | v77,83.5 77,83 | v28.9,37.6 31,40 31,65 33,69 33,80 v30,82.5 50,103 | 54,99 MINUS.1
  other vias: 51,64.25 54,95 75,19
  pour Bottom (isolate 2): 90,97 90,73 67,73 67,97
  pour Top (isolate 2, rank 5): 90,97 90,73 67,73 67,97
  pour Bottom (isolate 1, rank 4): 35,60 47,73 47,93 54,100 93,100 93,22 83,12 83,4 23,4 23,14 38,28 45,30 45,47 34,47
  pour Top (isolate 1, rank 4): 47,93 54,100 94,100 92,23 82,4 20,4 20,10 40,30 45,30 45,34 45.5,34 45.5,49 27,49 25,52 36,69 37,70 42,70 45,73 47,73
  pour Bottom (isolate 2, rank 3, no thermals): 26,101 26,121 35,121 38,119 38,108 39,107 45.8,107 48,110 56,110 56,107 65,107 65,110 80,110 81,109 81,101
  pour Top (isolate 2, rank 2, no thermals): 26,121 38,121 38,108 39,107 46,107 46,110.5 56,110.5 56,107 65,107 65,110.5 81,110.5 81,101 35,101 26,110
N$1
  Top 0.5: Q5.3 27.02,14.02 26.4,13.2 26.4,11.13 Q11.C 25.9,10.63 25.9,9.4 23.27,6.77 VENT.1
N$2
  Top 0.5: Q5.1 29.45,12.29 Q11.B | Q11.B 28.02,10 | R2.2 27.9,8.9 28,9 28,10.44 Q11.B
N$3
  Top 0.5: JP7.17 31.68,11.68 31,11 31,9 30,8 30,7.1 R2.1
N$4
  Bottom 0.5: 80,90 81,90
N$5  (1 unrouted)
N$6
  Top 0.5: TRAFO.1 75.95,94.25 R3.2
N$7
  Top 0.5: C9.1 85.15,94.3 TRAFO.2
N$8
  Top 0.5: R11.2 88.2,90.15 R6.2
N$9  (via drill 0.6 pad 1.5)
  Top 0.5: R21.1 34.9,59.1 34.8,59 v34.5,59 35,58.5 35,55.63 FUSE.2 | FUSE.5 37.51,53 36,52 v34.5,51 35.4,50.6 R22.2
  Bottom 0.5: v34.5,51 v34.5,59
N$10
  Top 0.5: R8.2 78.8,80.1 R13.1 D3.A
N$12
  Top 0.5: FAST.8 36.55,36.55 30,30 | 29.66,29.66 30,30 | 2HIDRV.3 29.66,30.34 30,30 | 29.66,29.66 2HIDRV.2 | R36.1 29.66,29.66
N$13  (via drill 0.6)
  Top 3: v6,65 8,65
  Bottom 3: v6,65 8,65
N$14
  Top 0.5: R20.2 27.1,59.25 D19.1
N$16
  Top 0.5: 30,44 30,44.2 | 30,44.2 29.9,43.97 | 2LODRV.2 30.33,43.67 30,44 | 30,44.2 30,44 | 2LODRV.3 30.33,44.53 30,44.2 | R35.1 30,44 | FAST.1 39.45,45.45 38,44 30,44
N$17
  Top 0.5: R25.2 R26.2 37.1,20.8 38.4,20.8 39.2,20 VREG.1
N$18
  Top 0.5: Q10.E 34.8,63.25 40.6,63.25 D20.3 D21.3
N$20
  Top 0.5: D1.C 21.7,33.8 D5.K
N$23
  Top 0.5: R27.1 88.2,7.85 R9.2
N$24
  Top 0.5: D6.C 24.7,82.9 D7.K
N$25
  Top 0.5: Q10.B 31.95,61.05 R19.1
N$26
  Top 0.5: R23.2 29,60.9 Q10.C
N$29
  Top 0.5: R28.1 86,15 85,16 84.4,16 R29.2 R10.2 82,15.6 R12.E
N$30
  Top 0.5: R12.A 84.49,8.46 R9.1 85,8.05 85,10 86,11 R28.2
O_IFB  (via drill 0.6 pad 1.5)
  Top 0.5: C17.1 D19.3 R23.1 R24.2 29.27,54.37 FUSE.3 FUSE.6 39.63,54.37 v42,53 | v72,16 72,13.32 JP7.1
  Bottom 0.5: v42,53 63,53 64,52 64,24 v72,16
PUMP+  (1 unrouted)
  Top 0.406: P+2.1 P+1.1
  Top 0.5: P+1.1 88,75 89,76 89,83 88.65,84.35 R11.1 84.4,85.35 TRAFO.3 | P+2.1 85,73 85.38,73.27 | C4.+ 42.46,114 | Q4.D M4.D 6,77.5 8,77.5 | M3.D 6.9,16 7,16.1 | C20.1 14.96,90.46 15.5,91
  Top 3: 15.5,91 15.5,88 | 6,77.5 8,77.5 | 5.9,16.1 7,16.1 8.9,16.1 | 14,63 15,63
  Bottom 0.5: C1.+ 83,106 83,101 91,101 92,100 92,74 90,72 P+2.1 | 14,78 14,88 13.46,88.54 C20.1 | 14,78 9,78 | 11,77.5 14,77.5 | M4.D 11,77.5 | 11,77.5 14,78 | M3.D 17,16 17,54 16.54,54.46 C19.1
  pour Top (isolate 2, rank 2): 89,86 89,73 85,73 85,77 88,77 88,84.6 84,84.6 84,86
  pour Bottom (isolate 2, rank 2): 38,121 92,121 92,108 83,108 79,112 66,112 63,109 63,108 60,108 60,110 58,112 45,112 44,111 44,108 18,108 17,107 17,84 13,84 13,99 14,101 14,112 37,112 38,113
  pour Top (isolate 2, rank 4): 40,121 92,121 92,108 83,108 79,112 66,112 63,109 63,108 60,108 60,110 58,112 45,112 44,111 44,108 17,108 16,107 11,109 14,112 37,112 38,113
  pour Bottom (isolate 2, rank 4): 3,18 13,18 13,74 12,76 9,76 7,78 9,80 12,80 13,81 13,90 14,91 15,91 18,88 20,52 20,16 17,13 4,13 3,14
RED  (via drill 0.6 pad 1.5, 2.2 pad 1.5)  (2 unrouted)
  Top 0.5: HVL1.2 v53,26 | R31.1 11.45,23.55 v9,26 | Q1.D M1.D 6,46.5
  Top 3: 6,46.5 8,46.5 | 6,60 8,60
  Route2 0.5: v53,26 53,25
  other vias: 6,30
  pour Top (isolate 2): 4,21 4,35 12,35 12,24 13,24 11,22 9,22 8,21
  pour Bottom (isolate 2): 5,61 9,61 11,55 11,50 14,48 14,20 4,20 4,35 10,41 5,48 9,48 9,56 5,56
SCR2
  pour Top (isolate 2): 89,53 89,50 75,50 75,53
  pour Bottom (isolate 2): 89,53 89,50 75,50 75,53
SD  (via drill 0.6 pad 1.5)
  Top 0.5: FAST.13 48.37,41.63 47.5,42 47.5,55 47,55 | 47,55 43.27,55 42.27,55.73 v42,56 41.37,55.63 FUSE.7 | SLOW.13 57.37,80.64 60,78 v60,55 | R37.1 48,54 47,55
  Bottom 0.5: v42,56 44,56 45,55 v60,55
SNUB1
  pour Top (isolate 2, rank 3): 73,53 73,41 66,41 66,53
  pour Bottom (isolate 2, rank 3): 73,53 73,41 66,41 66,53
SNUB2
  pour Top (isolate 2, rank 3): 73,37 73,25 66,25 66,37
  pour Bottom (isolate 2, rank 3): 73,37 73,25 66,25 66,37
SOURCE
  pour Top (isolate 2): 89,37 89,34 75,34 75,37
  pour Bottom (isolate 2): 89,37 89,34 75,34 75,37
TFB  (via drill 0.6 pad 1.5)
  Top 0.5: C2.1 34,13.22 JP7.16 34.2,10.78 v34.3,10.5 | NTC.1 32.63,7.63 v32.6,8.1
  Route2 0.5: 31.68,4.95 NTC.1
  Bottom 0.5: v32.6,8.1 32.6,9.6 v34.3,10.5
V12  (via drill 0.6 pad 1.5)
  Top 0.406: 43.4,31.5 43.4,31.6 v45.8,34
  Top 0.5: C7.+ 82.45,77.45 81,76 78,76 V12_1.1 | V12_1.1 R13.2 | D9.K 74,78 V12_1.1 | 31,41 33,41 C16.1 35.55,42.45 v36.7,41.9 37.6,41.8 39.2,42.9 39.7,42.91 FAST.3 | 31,41 24,41 | 24,41 23.7,41 | FUSE.8 37.7,57.7 v37,59 37.1,59.6 R21.2 | v44.4,10.5 44.3,12.92 JP7.12 | JP7.12 44.2,13.18 | JP7.12 44.34,13.04 VREG1.3 44.3,16.14 44.3,16.8 44,17.1 44,18 | VENT.2 20.73,6.27 v20.7,8.7 | 2LODRV.8 23.67,41.33 24,41 | 2LODRV.1 30.33,41.67 31,41 | 1LODRV.8 24.3,96.89 24.46,96.73 24.46,95.88 27.29,93.05 28,92.34 28.47,92.34 1LODRV.1 30,91.89 30,91 31.5,89.5 | VREG.3 43.8,18.2 44,18 | C8.+ 44.1,17.9 44,18 | D8.A 43.4,31.5 43.9,31.5 43.9,31.7 | SLOW.3 39.09,81.91 37,84 | 37,84 31.5,89.5 | C15.1 32.1,90.1 31.5,89.5 | C13.1 47,32 46,34 46,33.4 v45.8,34 | D10.A 34.4,68.6 v37,68.5 37.45,69 C14.1 | v37,82 36,83 37,84
  Top 1: v69,68.5 69.5,69 77,69 V12_2.1 V12_1.1
  Bottom 0.5: v37,68.5 v37,59 37,42 | v37,68.5 v37,82 | v36.7,41.9 37,42 | v37,68.5 v69,68.5 | v44.4,10.5 44.3,16.8 44.1,17 42,20 36,20 | v20.7,8.7 21,9 21,12 29,20 36,20 | v36.7,41.9 36.1,42 37,42 | v36.7,41.9 42.9,41.9 44,40 44,34 | 36,20 36,27 40,31 44,31 44,34 | 44,34 v45.8,34 R38.2
  pour Top (isolate 2): 83,79 83,73 74,73 74,78 81,78
  pour Top (isolate 1): 23,98 23,96 36,83 37,83 38,84 24,98
  pour Top (isolate 1.5): 35,69 39,69 39,67 35,67
  pour Top (isolate 1.5): 23,42 37,42 37,40 22,40 22,42
VB1
  Top 0.5: SLOW.7 43.17,76.83 44,76 44,74 43,72.5 37.5,72.5 C21.1 37.24,71.89 37.24,71.24 37,71 36.49,71.51 34.21,71.51 1HIDRV.1 | 1HIDRV.8 27.55,71.45 28,71 | D10.K 29.6,69.6 30,70
  pour Top (isolate 1.5, rank 2): 26,72 37,72 37,71 33,71 31,69 26,69
VB2
  Top 0.5: 33.18,29 34,29 35,30 | 35,30 36,31 35.99,31.01 | 35,30 36.4,31 D8.K 38.5,32.5 39,35 43.5,35 43.5,37.5 43.2,37.8 42.83,37.83 FAST.7 | 2HIDRV.1 31.45,28.55 32,28 | 2HIDRV.8 26.95,24.05 28,23
  pour Top (isolate 1.5): 27,23 28,22 37,31 37,33 36,33 27,24
VDD  (via drill 0.6 pad 1.5)
  Top 0.5: 41.9,23.1 R26.1 | 41.9,23.1 42,23 42,21.6 41.6,21.2 41.6,19 40.4,17.8 39.5,17.8 39.26,17.56 VREG1.1 39.3,16.06 JP7.14 39.3,11.3 v39.4,10.5 | VREG.4 41.5,23.5 41.9,23.1 | v35.2,8 35,6.07 NTC.2 | v45.5,22.7 C6.+
  Bottom 0.5: v39.4,10.5 39.4,10.6 v35.2,8 | R18.1 51,31 49,29 49,25.88 46.03,22.91 45.71,22.91 v45.5,22.7
  pour Top (isolate 0.8): 39,25 47,25 47,24 45,20 43,20 43,19 40,15 37,15 37,23
VDD1  (via drill 0.6)
  Top 0.5: SLOW.11 53.91,78.09 55,77 v55,49 | v52,35 53,36 53,38 52,39 51,39 50.2,39 FAST.11
  Bottom 0.5: v55,49 55,38 v52,35 52,34.65 R18.2 50.35,33.65 50,34 R38.1
VFB
  Top 0.5: R12.S 80,11 76,4.5 39,4.5 38.2,5.2 C10.1 36.76,9.84 JP7.15
VS3
  Top 0.5: ROUT6.1 19.25,28.1 | 19.25,28.1 19.3,28.51 | 2HIDRV.4 28.55,31.45 28,32 | FAST.6 36.09,39.09 33,36 32.81,35 C22.2 | 2HIDRV.5 24.05,26.95 23,28 | 23,28 23.9,28 | 23,28 19.35,28 19.25,28.1
  pour Top (isolate 1.5): 18,31 23,31 24,30 25,30 30,35 34,38 35,37 25,27 22,26 18,28
VS4
  Top 0.5: 1HIDRV.5 27.34,76.4 27.34,77 27,77 | SLOW.6 38.09,78.09 37,77 37,76.2 | 37,76.2 C21.2 | 27,77 21,77 ROUT8.1 D6.A | 37,76.2 1HIDRV.4 33.21,77.19 | 27,77 27.19,77.19
  pour Top (isolate 1.5): 18,81 22,81 23,80 23,79 24,78 38,78 38,76 21,76 18,79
